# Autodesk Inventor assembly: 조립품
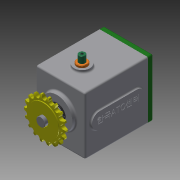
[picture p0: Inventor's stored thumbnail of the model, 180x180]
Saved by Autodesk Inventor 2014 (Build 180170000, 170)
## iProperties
Created: 2018-12
Part Number: 조립품
Document SubType Name: Assembly
Designer: kh
Author: kh
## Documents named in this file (16)
- C:\Users\kh\Desktop\381207V1059\답안조립품.iam
- C:\Users\kh\Desktop\381207V1059\가변스프링.ipt
- C:\Users\kh\Desktop\381207V1059\본체.ipt
- C:\Users\kh\Desktop\381207V1059\멈춤나사 M3x8.ipt
- C:\Users\kh\Desktop\381207V1059\메인 기어 축.ipt
- C:\Users\kh\Desktop\381207V1059\베어링 608.ipt
- C:\Users\kh\Desktop\381207V1059\베어링 6003.ipt
- C:\Users\kh\Desktop\381207V1059\볼트 M4 x 10.ipt
- C:\Users\kh\Desktop\381207V1059\부시.ipt
- C:\Users\kh\Desktop\381207V1059\서브 기어 축.ipt
- C:\Users\kh\Desktop\381207V1059\스프로킷.ipt
- C:\Users\kh\Desktop\381207V1059\슬라이더.ipt
- C:\Users\kh\Desktop\381207V1059\오일 실 8 22 7.ipt
- C:\Users\kh\Desktop\381207V1059\오일 실 17 32 8.ipt
- C:\Users\kh\Desktop\381207V1059\커버.ipt
- C:\Users\kh\Desktop\381207V1059\키 5 x 5 x 18.ipt
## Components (1 placed, 1 different names)
1. 가변스프링:1
